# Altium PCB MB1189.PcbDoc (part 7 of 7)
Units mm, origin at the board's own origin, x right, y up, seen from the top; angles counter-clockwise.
Board outline 60.03 x 127.03 mm, 6 copper layers (TOP, L2_GND, L3_VCC, L4_SIG, L5_GND, BOTTOM), stack 1.58 mm thick; 273 components, 264 nets, 1114 pads, 811 vias.
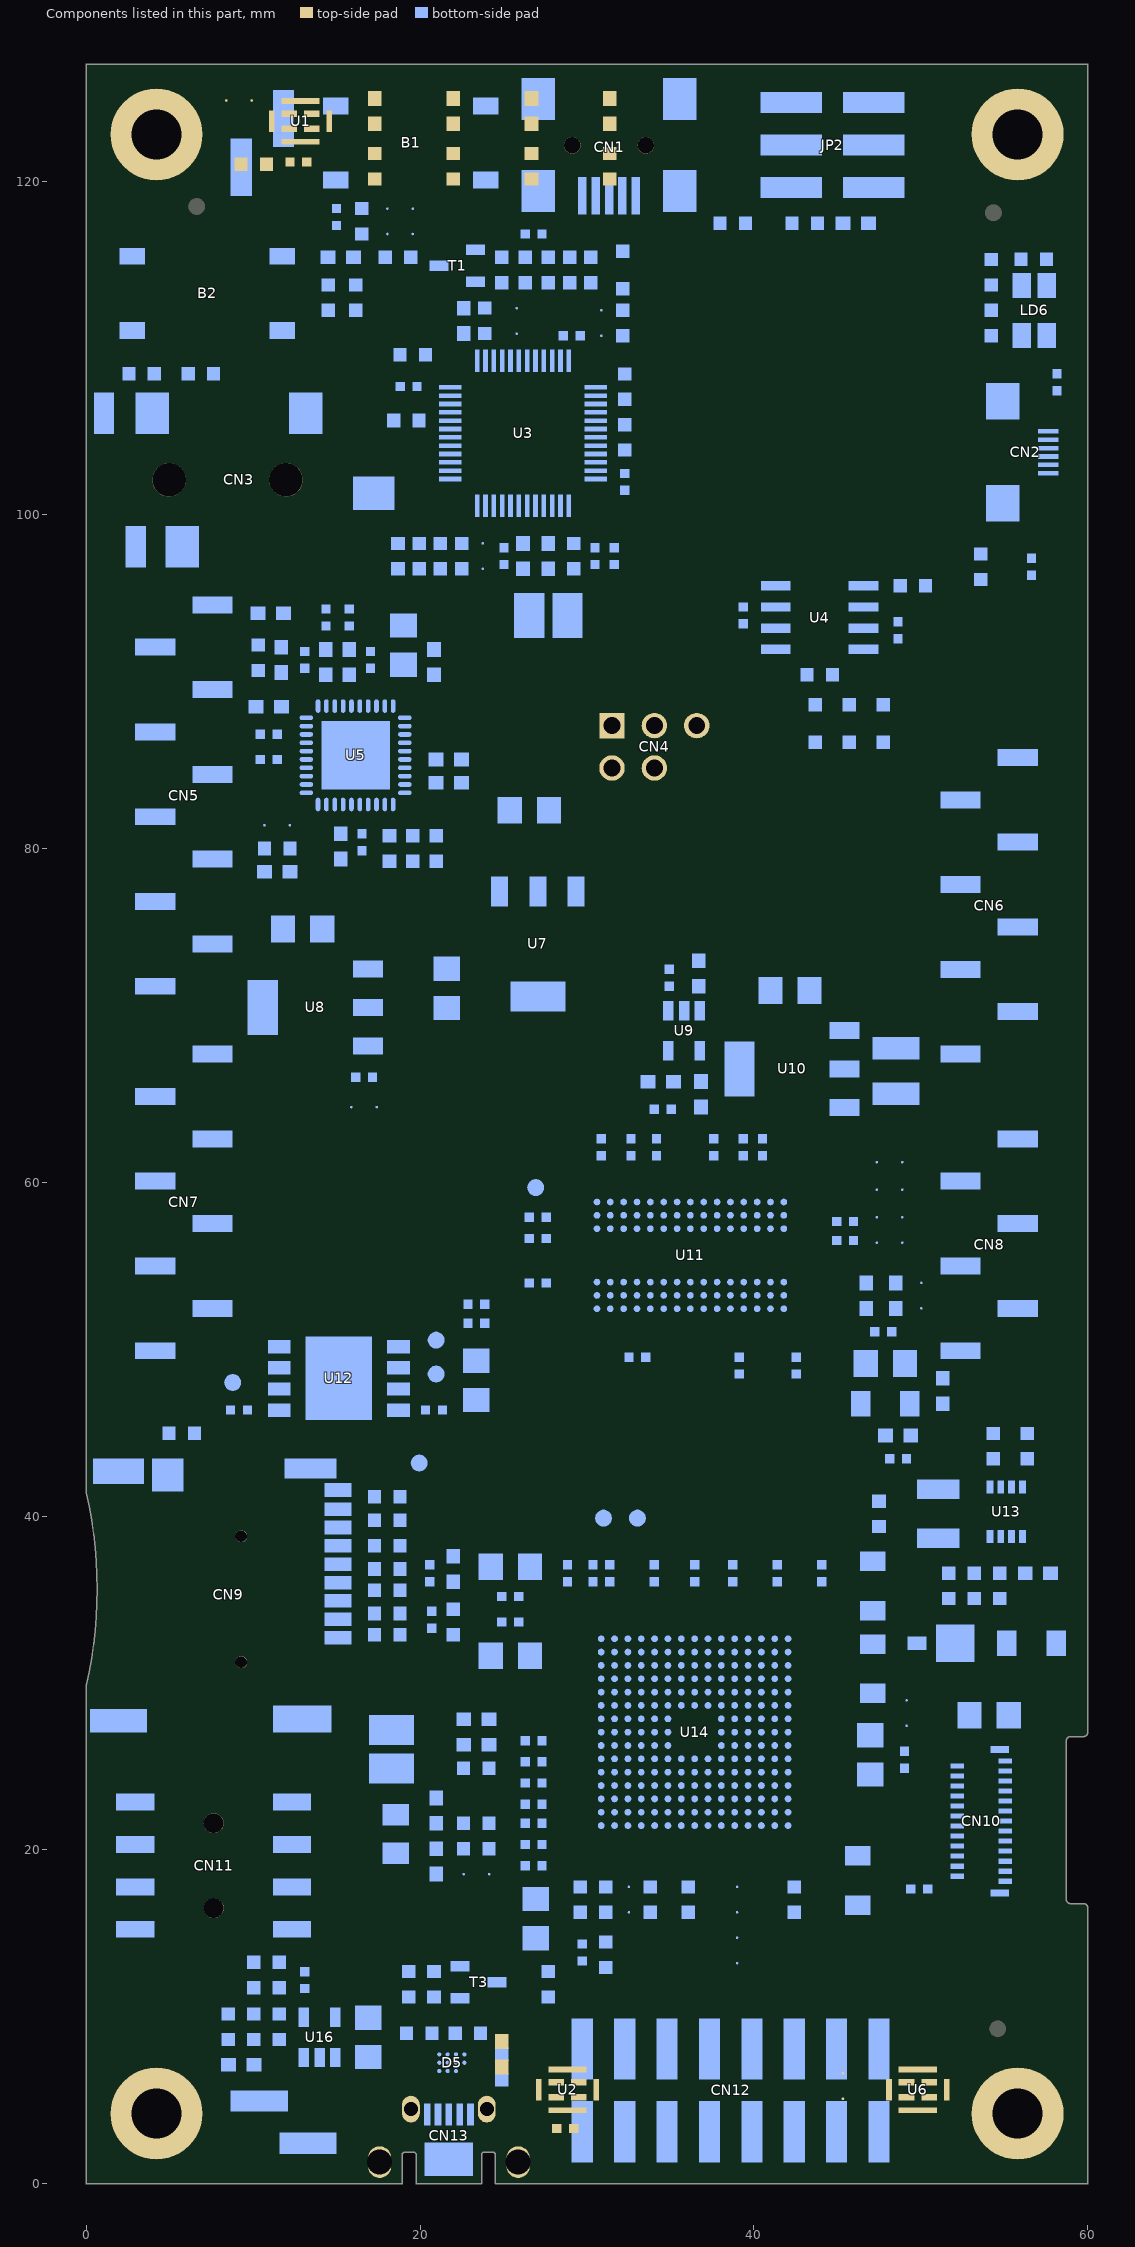
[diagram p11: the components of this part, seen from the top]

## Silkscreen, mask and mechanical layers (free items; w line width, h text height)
Top Overlay:
  lines w0.2: 10.795,122.834 10.541,122.834 10.541,121.793 11.659,121.793 11.659,122.047 ; 26.797,4.851 26.543,4.851 26.543,3.81 27.661,3.81 27.661,4.064 ; 47.799,4.851 47.545,4.851 47.545,3.81 48.663,3.81 48.663,4.064 ; 0,-0.042 0,29.804 ; 0,-0.042 18.917,-0.042 ; 0,-0.042 18.917,-0.042 ; 0,-0.042 0,29.804 ; 0,29.804 ccw(c-25.59,35.582) 0,41.361 ; 0,41.361 0,126.958 ; 0,41.361 0,126.958 ; 0,126.958 60,126.958 ; 0,126.958 60,126.958 ; 18.917,-0.042 18.917,1.744 ; 18.917,-0.042 18.917,1.744 ; 18.917,1.744 19.017,1.844 ; 18.917,1.744 19.017,1.844 ; 19.017,1.844 19.667,1.844 ; 19.017,1.844 19.667,1.844 ; 19.667,1.844 19.767,1.744 ; 19.667,1.844 19.767,1.744 ; 19.767,-0.042 19.767,1.744 ; 19.767,-0.042 23.667,-0.042 ; 19.767,-0.042 23.667,-0.042 ; 19.767,-0.042 19.767,1.744 ; 23.667,-0.042 23.667,1.744 ; 23.667,-0.042 23.667,1.744 ; 23.667,1.744 23.767,1.844 ; 23.667,1.744 23.767,1.844 ; 23.767,1.844 24.417,1.844 ; 23.767,1.844 24.417,1.844 ; 24.417,1.844 24.517,1.744 ; 24.417,1.844 24.517,1.744 ; 24.517,-0.042 24.517,1.744 ; 24.517,-0.042 60,-0.042 ; 24.517,-0.042 60,-0.042 ; 24.517,-0.042 24.517,1.744 ; 58.713,16.976 ccw(c58.967,16.976) 58.967,16.722 ; 58.713,16.976 ccw(c58.967,16.976) 58.967,16.722 ; 58.713,16.976 58.713,26.501 ; 58.713,16.976 58.713,26.501 ; 58.713,26.501 cw(c58.967,26.501) 58.967,26.755 ; 58.713,26.501 cw(c58.967,26.501) 58.967,26.755 ; 58.967,16.722 59.746,16.722 ; 58.967,16.722 59.746,16.722 ; 58.967,26.755 59.746,26.755 ; 58.967,26.755 59.746,26.755 ; 59.746,16.722 cw(c59.746,16.468) 60,16.468 ; 59.746,16.722 cw(c59.746,16.468) 60,16.468 ; 59.746,26.755 ccw(c59.746,27.009) 60,27.009 ; 59.746,26.755 ccw(c59.746,27.009) 60,27.009 ; 60,-0.042 60,16.468 ; 60,-0.042 60,16.468 ; 60,27.009 60,126.958 ; 60,27.009 60,126.958 ; 0.26,10.027 60,10.027 60,116.957 0.26,116.957 0.26,10.027 ; 11.43,58.547 11.43,59.944 12.827,59.944 12.827,58.547 11.43,58.547 ; 11.43,60.579 11.43,61.976 12.827,61.976 12.827,60.579 11.43,60.579 ; 21.336,5.8 22.479,5.8 22.479,9.356 21.336,9.356 21.336,5.8 ; 34,97.495 52,97.495 52,115.495 34,115.495 34,97.495
  text "H" at 46.68,121.509 h10
  text "J" at 35.56,118.727 h16
  text "C" at 47.74,118.601 h5
  text "www.st.com/stm32f4-discovery" at 12.99,117.92 h2.3
  text "S" at 11.752,60.762 h2
  text "B" at 11.705,58.712 h2
  text "MB1189C" at 9.11,7.87 h2.5
  text "STM32F469I-DISCO" at 29.93,7.85 h2.6
  text "VBUS" at 22.358,5.891 h1.4 r90
  text "E" at 34.303,4.755 h5
  text "F" at 38.98,4.25 h5
  text "I" at 14.38,3.169 h5
  text "G" at 8.59,3.141 h5
  text "S" at 36.357,0.48 h5
  text "TOP SILKSCREEN" at 55.499,-49.276 h1.52
  text ".GTO" at 97.5,-49.47 h1.52
Bottom Overlay:
  drawing of 324 lines, arcs and shapes, not listed
  text "RESET" at 18.662,125.652 h2
  text "GND" at 10.332,124.465 h1.7
  text "E5V" at 52.204,124.369 h2
  text "STLK" at 52.668,121.602 h2
  text "USBST-LINK" at 37.242,118.583 h2 r270
  text "USB" at 52.177,118.342 h2
  text "USER" at 4.666,117.082 h2
  text "5V" at 49.923,116.029 h2
  text "COM" at 58.761,113.577 h1.7 r270
  text "A" at 20.145,99.311 h1.7
  text "TS" at 59.514,98.602 h2
  text "AUDIO JACK" at 15.829,97.717 h2
  text "AUDIO JACK" at 15.829,97.717 h2
  text "D15" at 2.152,94.309 h1.6
  text "D14" at 1.945,91.941 h1.5
  text "A" at 49.982,89.434 h2
  text "AVDD" at 3.307,89.12 h1.6
  text "GND" at 2.578,86.58 h1.6
  text "D13" at 2.158,84.055 h1.6
  text "IOREF5" at 59.777,82.504 h1.7
  text "D12" at 2.161,81.508 h1.6
  text "NRST" at 59.845,79.976 h1.6
  text "D11" at 2.152,79.058 h1.6
  text "3V3" at 59.656,77.31 h1.6
  text "D10" at 2.179,76.421 h1.6
  text "5V" at 59.642,74.911 h1.6
  text "D9" at 1.499,74.015 h1.6
  text "GND" at 59.825,72.356 h1.6
  text "D8" at 1.508,71.221 h1.6
  text "GND" at 59.907,69.9 h1.6
  text "VIN" at 59.845,67.404 h1.6
  text "D7" at 1.496,67.166 h1.6
  text "B" at 10.555,65.002 h2
  text "D6" at 1.508,64.615 h1.6
  text "D5" at 1.487,62.338 h1.6
  text "A0" at 59.749,62.206 h1.6
  text "B" at 24.994,60.833 h1.5
  text "A1" at 59.749,59.894 h1.6
  text "D4" at 1.523,59.774 h1.6
  text "B" at 24.994,58.801 h1.5
  text "D3" at 1.493,57.164 h1.6
  text "A2" at 59.749,57.089 h1.6
  text "A3" at 59.749,54.696 h1.6
  text "D2" at 1.496,54.597 h1.6
  text "D1" at 1.487,52.201 h1.6
  text "A4" at 59.749,52.167 h1.6
  text "D0" at 1.514,49.495 h1.6
  text "A5" at 59.741,49.511 h1.6
  text "uSB" at 8.94,42.982 h2
  text "B" at 17.395,42.522 h2
  text "C" at 27.033,27.552 h2
  text "RFEEPROM" at 7.832,24.624 h1.8
  text "C" at 15.002,23.784 h2
  text "DSI  LCD" at 57.082,18.298 h2 r270
  text "FAULT" at 7.421,7.825 h1.9
  text "EXT" at 51.695,5.142 h2
  text "IDD" at 8.966,0.812 h2
  text "USB USER" at 26.992,0.567 h2 r270
  text ".GBO" at -7.9,-49.12 h1.8
  text "BOTTOM SILKSCREEN" at 27.457,-49.276 h1.8
Top Paste:
  text "SOLDER PASTE (PRIMARY)" at 55.499,-49.276 h1.52
Bottom Paste:
  text "BOTTOM SOLDER PASTE" at 55.499,-49.276 h1.52
Top Solder:
  text "TOP SOLDER MASK" at 55.499,-49.276 h1.52
  text ".GTS" at 97.47,-49.36 h1.52
Bottom Solder:
  text "BOTTOM SOLDER MASK" at 55.499,-49.276 h1.52
  text ".GBS" at 97.33,-49.29 h1.52
OUTLINE:
  lines w0.025: 0,29.845 0,0 18.917,0 18.917,1.785 19.017,1.885 19.667,1.885 19.767,1.785 19.767,0 23.667,0 23.667,1.785 23.767,1.885 24.417,1.885 24.517,1.785 24.517,0 60,0 60,16.51 ccw(c59.746,16.51) 59.746,16.764 58.967,16.764 cw(c58.967,17.018) 58.713,17.018 58.713,26.543 cw(c58.967,26.543) 58.967,26.797 ; 0,29.845 ccw(c-25.59,35.623) 0,41.402 ; -90.424,-128.016 -90.424,283.464 ; -90.424,-128.016 458.216,-128.016 ; -90.424,-128.016 -90.424,283.464 ; -90.424,-128.016 458.216,-128.016 ; -90.424,283.464 458.216,283.464 ; -90.424,283.464 458.216,283.464 ; -82.804,-120.396 326.136,-120.396 ; -82.804,-120.396 -82.804,275.844 ; -82.804,-120.396 -82.804,275.844 ; -82.804,-120.396 326.136,-120.396 ; -82.804,275.844 450.596,275.844 ; -82.804,275.844 450.596,275.844 ; 0,127 0,41.402 0,127 ; 0,127 60,127 ; 0,127 60,127 ; 58.967,26.797 59.746,26.797 ; 58.967,26.797 59.746,26.797 ; 59.746,26.797 ccw(c59.746,27.051) 60,27.051 ; 60,27.051 60,127 ; 60,27.051 60,127 ; 178.816,-116.586 188.976,-116.586 ; 178.816,-116.586 183.896,-128.016 ; 178.816,-116.586 183.896,-121.666 ; 178.816,-116.586 183.896,-121.666 ; 178.816,-116.586 188.976,-116.586 ; 178.816,-116.586 183.896,-128.016 ; 183.896,-128.016 188.976,-116.586 ; 183.896,-128.016 183.896,-110.236 183.896,-128.016 ; 183.896,-128.016 183.896,-120.396 183.896,-128.016 ; 183.896,-128.016 188.976,-116.586 ; 183.896,-121.666 188.976,-116.586 ; 183.896,-121.666 188.976,-116.586 ; 326.136,-120.396 450.596,-120.396 ; 326.136,-120.396 450.596,-120.396 ; 450.596,-120.396 450.596,123.444 ; 450.596,-120.396 450.596,123.444 ; 450.596,123.444 450.596,219.964 450.596,123.444 ; 450.596,275.844 450.596,82.804 450.596,275.844 ; 458.216,-128.016 458.216,283.464 ; 458.216,-128.016 458.216,283.464 ; -90.424,-21.336 -82.804,-21.336 -90.424,-21.336 ; -90.424,77.724 -82.804,77.724 -90.424,77.724 ; -90.424,176.784 -82.804,176.784 -90.424,176.784 ; 6.096,-128.016 6.096,-120.396 6.096,-128.016 ; 6.096,275.844 6.096,283.464 6.096,275.844 ; 94.996,-128.016 94.996,-120.396 94.996,-128.016 ; 94.996,275.844 94.996,283.464 94.996,275.844 ; 183.896,275.844 183.896,283.464 183.896,275.844 ; 272.796,-128.016 272.796,-120.396 272.796,-128.016 ; 272.796,275.844 272.796,283.464 272.796,275.844 ; 361.696,-128.016 361.696,-120.396 361.696,-128.016 ; 361.696,275.844 361.696,283.464 361.696,275.844 ; 450.596,-21.336 458.216,-21.336 450.596,-21.336 ; 450.596,77.724 458.216,77.724 450.596,77.724 ; 450.596,176.784 458.216,176.784 450.596,176.784
  text "6" at -37.084,278.384 h3.3
  text "6" at -37.084,278.384 h3.3
  text "5" at 51.816,278.384 h3.3
  text "5" at 51.816,278.384 h3.3
  text "4" at 140.716,278.384 h3.3
  text "4" at 140.716,278.384 h3.3
  text "3" at 229.616,278.384 h3.3
  text "3" at 229.616,278.384 h3.3
  text "2" at 318.516,278.384 h3.3
  text "2" at 318.516,278.384 h3.3
  text "1" at 407.416,278.384 h3.3
  text "1" at 407.416,278.384 h3.3
  text "D" at -87.884,219.964 h3.3
  text "D" at -87.884,219.964 h3.3
  text "D" at 453.136,219.964 h3.3
  text "D" at 453.136,219.964 h3.3
  text "C" at -87.884,120.904 h3.3
  text "C" at -87.884,120.904 h3.3
  text "C" at 453.136,120.904 h3.3
  text "C" at 453.136,120.904 h3.3
  text "B" at -87.884,26.924 h3.3
  text "B" at -87.884,26.924 h3.3
  text "B" at 453.136,26.924 h3.3
  text "B" at 453.136,26.924 h3.3
  text "A" at -87.884,-79.756 h3.3
  text "A" at -87.884,-79.756 h3.3
  text "A" at 453.136,-79.756 h3.3
  text "A" at 453.136,-79.756 h3.3
  text "6" at -37.084,-125.476 h3.3
  text "6" at -37.084,-125.476 h3.3
  text "5" at 51.816,-125.476 h3.3
  text "5" at 51.816,-125.476 h3.3
  text "4" at 140.716,-125.476 h3.3
  text "4" at 140.716,-125.476 h3.3
  text "3" at 229.616,-125.476 h3.3
  text "3" at 229.616,-125.476 h3.3
  text "2" at 318.516,-125.476 h3.3
  text "2" at 318.516,-125.476 h3.3
  text "1" at 407.416,-125.476 h3.3
  text "1" at 407.416,-125.476 h3.3
DIMENSION:
  lines w0.025: -17.486,0 -2.5,0 ; -17.486,127 -2.5,127 ; -9.612,67.691 5.056,67.691 ; -9.612,71.755 1.627,71.755 ; 0,129.5 0,134.58 ; 58.317,62.611 73.62,62.611 ; 58.317,85.471 73.62,85.471 ; 60,129.5 60,134.58 ; 71.12,105.936 71.12,85.471 ; -14.986,0 -14.986,66.04 -14.986,127 ; -14.986,0 -14.361,4 -15.611,4 -14.986,0 ; -14.986,127 -15.611,123 -14.361,123 -14.986,127 ; -7.112,67.691 -7.112,69.088 -7.112,71.755 ; -7.112,67.691 -7.737,63.691 -6.487,63.691 -7.112,67.691 ; -7.112,71.755 -6.487,75.755 -7.737,75.755 -7.112,71.755 ; 0,132.08 30.48,132.08 60,132.08 ; 0,132.08 4,131.455 4,132.705 0,132.08 ; 60,132.08 56,132.705 56,131.455 60,132.08 ; 71.12,62.611 71.12,85.471 ; 71.12,62.611 71.745,66.611 70.495,66.611 71.12,62.611 ; 71.12,62.611 71.12,85.471 ; 71.12,85.471 70.495,81.471 71.745,81.471 71.12,85.471
  text "60" at 28.727,133.286 h2.16
  text "22.86" at 69.913,95.122 h2.16 r90
  text "4.06" at -8.319,65.481 h2.16 r90
  text "127" at -16.192,63.36 h2.16 r90
  text "FAB DARWING & DRILL LEGEND" at 55.01,-49.33 h1.42
PLACE_BOUND_TOP:
  region: 8.135,118.491 8.106,118.79 8.019,119.077 7.877,119.342 7.687,119.574 7.455,119.764 7.19,119.906 6.903,119.993 6.604,120.022 6.305,119.993 6.018,119.906 5.842,119.812 5.753,119.764 5.521,119.574 5.331,119.342 5.189,119.077 5.102,118.79 5.073,118.491 5.102,118.192 5.189,117.905 5.331,117.64 5.521,117.408 5.753,117.218 5.842,117.17 6.018,117.076 6.305,116.989 6.604,116.96 6.903,116.989 7.19,117.076 7.455,117.218 7.687,117.408 7.877,117.64 8.019,117.905 8.106,118.192 8.135,118.491
  region: 55.887,118.11 55.858,118.409 55.771,118.696 55.629,118.961 55.439,119.193 55.207,119.383 54.942,119.525 54.655,119.612 54.356,119.641 54.057,119.612 53.77,119.525 53.594,119.431 53.505,119.383 53.273,119.193 53.083,118.961 52.941,118.696 52.854,118.409 52.825,118.11 52.854,117.811 52.941,117.524 53.083,117.259 53.273,117.027 53.505,116.837 53.594,116.789 53.77,116.695 54.057,116.608 54.356,116.579 54.655,116.608 54.942,116.695 55.207,116.837 55.439,117.027 55.629,117.259 55.771,117.524 55.858,117.811 55.887,118.11
  region: 56.141,9.271 56.112,9.57 56.025,9.857 55.883,10.122 55.693,10.354 55.461,10.544 55.196,10.686 54.909,10.773 54.61,10.802 54.311,10.773 54.024,10.686 53.848,10.592 53.759,10.544 53.527,10.354 53.337,10.122 53.195,9.857 53.108,9.57 53.079,9.271 53.108,8.972 53.195,8.685 53.337,8.42 53.527,8.188 53.759,7.998 53.848,7.95 54.024,7.856 54.311,7.769 54.61,7.74 54.909,7.769 55.196,7.856 55.461,7.998 55.693,8.188 55.883,8.42 56.025,8.685 56.112,8.972 56.141,9.271
PLACE_BOUND_BOTTOM:
  region: 8.135,118.491 8.106,118.79 8.019,119.077 7.877,119.342 7.687,119.574 7.455,119.764 7.19,119.906 6.903,119.993 6.604,120.022 6.305,119.993 6.018,119.906 5.842,119.812 5.753,119.764 5.521,119.574 5.331,119.342 5.189,119.077 5.102,118.79 5.073,118.491 5.102,118.192 5.189,117.905 5.331,117.64 5.521,117.408 5.753,117.218 5.842,117.17 6.018,117.076 6.305,116.989 6.604,116.96 6.903,116.989 7.19,117.076 7.455,117.218 7.687,117.408 7.877,117.64 8.019,117.905 8.106,118.192 8.135,118.491
  region: 55.887,118.11 55.858,118.409 55.771,118.696 55.629,118.961 55.439,119.193 55.207,119.383 54.942,119.525 54.655,119.612 54.356,119.641 54.057,119.612 53.77,119.525 53.594,119.431 53.505,119.383 53.273,119.193 53.083,118.961 52.941,118.696 52.854,118.409 52.825,118.11 52.854,117.811 52.941,117.524 53.083,117.259 53.273,117.027 53.505,116.837 53.594,116.789 53.77,116.695 54.057,116.608 54.356,116.579 54.655,116.608 54.942,116.695 55.207,116.837 55.439,117.027 55.629,117.259 55.771,117.524 55.858,117.811 55.887,118.11
  region: 56.141,9.271 56.112,9.57 56.025,9.857 55.883,10.122 55.693,10.354 55.461,10.544 55.196,10.686 54.909,10.773 54.61,10.802 54.311,10.773 54.024,10.686 53.848,10.592 53.759,10.544 53.527,10.354 53.337,10.122 53.195,9.857 53.108,9.57 53.079,9.271 53.108,8.972 53.195,8.685 53.337,8.42 53.527,8.188 53.759,7.998 53.848,7.95 54.024,7.856 54.311,7.769 54.61,7.74 54.909,7.769 55.196,7.856 55.461,7.998 55.693,8.188 55.883,8.42 56.025,8.685 56.112,8.972 56.141,9.271
ASSEMBLY_TOP:
  text "TOP ASSEMBLY" at 55.499,-49.276 h1.52
  text ".GTO" at 97.43,-49.36 h1.52
ASSEMBLY_BOTTOM:
  text "ASSEMBLY (SECONDARY)" at 31.115,-49.276 h1.52
TOP_TITLE_BLOCK:
  circle w0.254: c133.432,-56.1 r1.3
  region: 118.954,-57.193 108.198,-57.193 109.191,-54.7 117.049,-54.7 117.498,-53.941 119.706,-56.489
  region: 132.957,-48.863 117.43,-48.863 116.736,-50.639 115.525,-51.864 114.128,-50.004 114.128,-48.353 115.271,-46.956 116.707,-46.577 132.957,-46.577
  lines w0.254: 109.191,-54.7 117.983,-54.7 114.917,-51.162 cw(c116.721,-49.218) 116.961,-46.577 133.725,-46.577 132.963,-48.863 ; 112.505,-46.33 cw(c114.931,-47.301) 115.168,-44.698 ; 112.544,-46.298 108.198,-57.193 127.52,-57.193 ccw(c127.769,-54.458) 130.318,-55.478 ; 114.284,-50.233 119.706,-56.489 ; 114.538,-50.233 119.843,-56.354 ; 114.538,-49.979 119.843,-56.1 ; 114.636,-48.863 127.629,-48.863 ; 114.665,-49.852 119.97,-55.973 ; 114.792,-49.725 120.097,-55.846 ; 114.919,-49.598 120.224,-55.719 ; 115.046,-49.471 120.351,-55.592 ; 115.101,-47.518 120.406,-53.639 ; 115.169,-44.698 134.619,-44.698 130.319,-55.476 ; 115.173,-49.344 120.423,-55.402 ; 115.173,-49.09 120.478,-55.211 ; 115.173,-48.836 120.478,-54.957 ; 115.173,-47.947 120.478,-54.068 ; 115.3,-48.709 120.605,-54.83 ; 115.3,-48.328 120.605,-54.449 ; 116.672,-54.713 ccw(c116.777,-54.178) 117.074,-53.721 ; 117.758,-48.85 ccw(c117.732,-49.417) 117.402,-49.879 119.767,-52.608 cw(c117.963,-54.552) 118.695,-57.101 ; 124.039,-56.989 126.929,-48.609 ; 124.262,-56.939 127.131,-48.618 ; 124.389,-56.939 127.258,-48.618 ; 124.643,-56.939 127.512,-48.618 ; 124.897,-56.939 127.766,-48.618 ; 125.151,-56.939 128.02,-48.618 ; 125.405,-56.939 128.274,-48.618 ; 125.659,-56.939 128.528,-48.618 ; 125.913,-56.939 128.782,-48.618 ; 126.167,-56.939 129.036,-48.618 ; 126.375,-56.989 129.265,-48.609 ; 129.265,-48.863 132.957,-48.863 ; 132.289,-48.861 133.051,-46.575 ; 132.455,-48.863 133.217,-46.577 ; 132.709,-48.863 133.471,-46.577
  lines w0.3: 46.427,-56.079 106.427,-56.079 ; 46.427,-51.079 106.427,-51.079 ; 46.427,-46.079 106.427,-46.079 ; 86.427,-61.079 86.427,-46.079 ; 106.427,-61.079 106.427,-41.079 ; 124.039,-56.989 126.375,-56.989 ; 46.427,-61.079 136.427,-61.079 136.427,-41.079 46.427,-41.079 46.428,-61.079
  text "Project: '.Board_Name'" at 47.428,-44.295 h3
  text "Layer:" at 47.428,-49.379 h3
  text "Gerber:" at 87.416,-49.379 h3
  text "Variant: '.VariantName'" at 47.428,-54.379 h3
  text "Ref: '.Board_Reference'" at 87.543,-54.379 h3
  text "R" at 132.924,-56.862 h1.52
  text "Date: '.Board_Document_Date'" at 47.428,-59.379 h3
  text "Rev: '.Board_PCB_Revision'" at 87.486,-59.379 h3
BOTTOM_TITLE_BLOCK:
  circle w0.254: c-43.658,-56.426 r1.3
  region: -29.18,-57.519 -18.424,-57.519 -19.417,-55.026 -27.275,-55.026 -27.724,-54.267 -29.932,-56.815
  region: -43.183,-49.189 -27.656,-49.189 -26.962,-50.965 -25.751,-52.19 -24.354,-50.33 -24.354,-48.679 -25.497,-47.282 -26.933,-46.903 -43.183,-46.903
  lines w0.254: -43.697,-46.903 -42.935,-49.189 ; -43.443,-46.903 -42.681,-49.189 ; -43.277,-46.901 -42.515,-49.187 ; -43.189,-49.189 -43.951,-46.903 -27.187,-46.903 cw(c-26.947,-49.544) -25.143,-51.488 -28.209,-55.026 -19.417,-55.026 ; -43.183,-49.189 -39.491,-49.189 ; -40.546,-55.802 -44.845,-45.024 -25.395,-45.024 ; -40.545,-55.804 ccw(c-37.995,-54.784) -37.747,-57.519 -18.424,-57.519 -22.77,-46.624 ; -39.491,-48.935 -36.602,-57.315 ; -39.262,-48.944 -36.393,-57.265 ; -39.008,-48.944 -36.139,-57.265 ; -38.754,-48.944 -35.885,-57.265 ; -38.5,-48.944 -35.631,-57.265 ; -38.246,-48.944 -35.377,-57.265 ; -37.992,-48.944 -35.123,-57.265 ; -37.855,-49.189 -24.862,-49.189 ; -37.738,-48.944 -34.869,-57.265 ; -37.484,-48.944 -34.615,-57.265 ; -37.357,-48.944 -34.488,-57.265 ; -37.155,-48.935 -34.266,-57.315 ; -30.831,-55.156 -25.526,-49.034 ; -30.831,-54.775 -25.526,-48.653 ; -30.704,-55.537 -25.399,-49.415 ; -30.704,-55.283 -25.399,-49.161 ; -30.704,-54.394 -25.399,-48.272 ; -30.65,-55.728 -25.399,-49.669 ; -30.632,-53.965 -25.327,-47.844 ; -30.577,-55.918 -25.272,-49.796 ; -30.45,-56.045 -25.145,-49.923 ; -30.323,-56.172 -25.018,-50.05 ; -30.196,-56.299 -24.891,-50.177 ; -30.069,-56.68 -24.764,-50.558 ; -30.069,-56.426 -24.764,-50.304 ; -29.932,-56.815 -24.51,-50.558 ; -28.922,-57.427 cw(c-28.189,-54.878) -29.993,-52.934 -27.628,-50.205 ccw(c-27.958,-49.743) -27.984,-49.176 ; -27.301,-54.047 ccw(c-27.003,-54.504) -26.898,-55.039 ; -25.394,-45.024 cw(c-25.157,-47.627) -22.731,-46.656
  lines w0.3: -36.602,-57.315 -34.266,-57.315 ; -16.841,-61.405 -16.841,-41.405 ; -16.841,-56.405 43.159,-56.405 ; -16.841,-51.405 43.159,-51.405 ; -16.841,-46.405 43.159,-46.405 ; 3.159,-61.405 3.159,-46.405 ; -46.841,-61.405 43.159,-61.405 43.159,-41.405 -46.841,-41.405 -46.841,-61.405
  text "Project: '.Board_Name'" at 41.965,-44.621 h3
  text "Gerber:" at 1.976,-49.705 h3
  text "Layer:" at 41.965,-49.705 h3
  text "Ref: '.Board_Reference'" at 1.976,-54.705 h3
  text "Variant: '.VariantName'" at 41.965,-54.705 h3
  text "R" at -43.15,-57.188 h1.52
  text "Rev: '.Board_PCB_Revision'" at 2.033,-59.705 h3
  text "Date: '.Board_Document_Date'" at 41.965,-59.705 h3
REVISION_BLOCK:
  lines w0.025: 345.186,244.094 345.186,275.844 345.186,244.094 ; 345.186,249.174 450.596,249.174 345.186,249.174 ; 345.186,254.254 450.596,254.254 345.186,254.254 ; 345.186,259.334 450.596,259.334 345.186,259.334 ; 345.186,264.414 450.596,264.414 345.186,264.414 ; 345.186,269.494 450.596,269.494 345.186,269.494 ; 355.346,244.094 355.346,269.494 355.346,244.094 ; 411.226,244.094 411.226,269.494 411.226,244.094 ; 430.276,244.094 430.276,269.494 430.276,244.094
REVISION_DATA:
  lines w0.025: 29.21,51.13 43.155,51.13 43.155,59.944 29.21,59.944 29.21,51.13 ; 29.87,20.472 43.028,20.472 43.028,33.63 29.87,33.63 29.87,20.472
  text "REVISIONS" at 384.556,272.034 h2.16
  text "REVISIONS" at 384.556,272.034 h2.16
  text "REV" at 347.726,265.684 h1.91
  text "REV" at 347.726,265.684 h1.91
  text "DESCRIPTION" at 361.696,265.684 h1.91
  text "DESCRIPTION" at 361.696,265.684 h1.91
  text "DATE" at 416.306,265.684 h1.91
  text "DATE" at 416.306,265.684 h1.91
  text "APPROVED" at 434.086,265.684 h1.91
  text "APPROVED" at 434.086,265.684 h1.91
  text "1.0" at 347.726,260.604 h1.91
  text "1.0" at 347.726,260.604 h1.91
  text "EDITION ORIGINALE" at 361.696,260.604 h1.91
  text "EDITION ORIGINALE" at 361.696,260.604 h1.91
  text "2008-**-**" at 412.496,260.604 h1.91
  text "2008-**-**" at 412.496,260.604 h1.91
  text "***" at 438.15,260.604 h1.91
  text "***" at 438.15,260.604 h1.91
PIN_NUMBER:
NCLEGEND-1-6:
  lines w0.025: 100.101,102.425 100.305,102.425 ; 100.203,102.324 100.203,102.527 ; 96.959,81.597 97.909,79.304 100.203,78.353 102.497,79.304 103.447,81.597 102.497,83.891 100.203,84.842 97.909,83.891 96.959,81.597 ; 99.695,86.55 100.203,86.296 100.711,86.55 100.711,87.058 100.203,87.312 99.695,87.058 99.695,86.55 ; 99.708,70.688 100.203,71.679 100.698,70.688 99.708,70.688 ; 99.847,76.391 100.203,76.746 100.559,76.391 100.203,76.035 99.847,76.391 ; 99.873,49.517 ccw(c99.873,50.355) 99.873,51.194 100.533,51.194 ccw(c100.533,50.355) 100.533,49.517 99.873,49.517 ; 100.051,92.011 100.127,91.859 100.279,91.859 100.355,92.011 100.279,92.164 100.127,92.164 100.051,92.011 ; 100.076,97.091 100.33,97.091 100.33,97.346 100.076,97.346 100.076,97.091 ; 100.165,54.8 ccw(c100.165,55.562) 100.165,56.325 100.241,56.325 ccw(c100.241,55.562) 100.241,54.8 100.165,54.8 ; 100.203,58.763 cw(c100.203,60.77) 100.203,62.776 cw(c100.203,60.77) 100.203,58.763 ; 100.203,64.783 cw(c100.203,65.977) 100.203,67.17 cw(c100.203,65.977) 100.203,64.783
  lines w0.152: 94.615,52.959 186.868,52.959 ; 94.615,58.166 186.868,58.166 ; 94.615,63.373 186.868,63.373 ; 94.615,68.58 186.868,68.58 ; 94.615,73.787 186.868,73.787 ; 94.615,78.994 186.868,78.994 ; 94.615,84.201 186.868,84.201 ; 94.615,89.408 186.868,89.408 ; 94.615,94.615 186.868,94.615 ; 94.615,99.822 186.868,99.822 ; 94.615,105.029 186.868,105.029 ; 94.615,110.236 186.868,110.236 ; 94.615,115.443 186.868,115.443 ; 105.791,47.752 105.791,110.236 ; 121.691,47.752 121.691,110.236 ; 145.466,47.752 145.466,110.236 ; 162.941,47.752 162.941,110.236 ; 177.267,47.752 177.267,110.236 ; 94.615,47.752 94.615,121.793 186.868,121.793 186.868,47.752 94.615,47.752
  text "DRILL CHART: TOP to BOTTOM" at 120.929,118.935 h1.91
  text "ALL UNITS ARE IN MILS" at 124.739,112.585 h1.91
  text "FIGURE" at 95.631,107.379 h1.91
  text "SIZE" at 110.693,107.379 h1.91
  text "TOLERANCE" at 126.721,107.379 h1.91
  text "PLATED" at 149.631,107.379 h1.91
  text "ROTATION" at 164.008,107.379 h1.91
  text "QTY" at 179.781,107.379 h1.91
  text "8.0" at 111.455,101.473 h1.91
  text "+3.0/-3.0" at 126.721,101.473 h1.91
  text "PLATED" at 149.631,101.473 h1.91
  text "-" at 169.342,101.473 h1.91
  text "243" at 179.781,101.473 h1.91
  text "10.0" at 110.693,96.266 h1.91
  text "+3.0/-3.0" at 126.721,96.266 h1.91
  text "PLATED" at 149.631,96.266 h1.91
  text "-" at 169.342,96.266 h1.91
  text "247" at 179.781,96.266 h1.91
  text "12.0" at 110.693,91.059 h1.91
  text "+3.0/-3.0" at 126.721,91.059 h1.91
  text "PLATED" at 149.631,91.059 h1.91
  text "-" at 169.342,91.059 h1.91
  text "321" at 179.781,91.059 h1.91
  text "40.0" at 110.693,85.852 h1.91
  text "+3.0/-3.0" at 126.721,85.852 h1.91
  text "PLATED" at 149.631,85.852 h1.91
  text "-" at 169.342,85.852 h1.91
  text "5" at 181.305,85.852 h1.91
  text "118.0" at 109.931,80.645 h1.91
  text "+3.0/-3.0" at 126.721,80.645 h1.91
  text "PLATED" at 149.631,80.645 h1.91
  text "-" at 169.342,80.645 h1.91
  text "4" at 181.305,80.645 h1.91
  text "28.0" at 110.693,75.438 h1.91
  text "+2.0/-2.0" at 126.721,75.438 h1.91
  text "NON-PLATED" at 146.583,75.438 h1.91
  text "-" at 169.342,75.438 h1.91
  text "2" at 181.305,75.438 h1.91
  text "39.0" at 110.693,70.231 h1.91
  text "+2.0/-2.0" at 126.721,70.231 h1.91
  text "NON-PLATED" at 146.583,70.231 h1.91
  text "-" at 169.342,70.231 h1.91
  text "2" at 181.305,70.231 h1.91
  text "47.0" at 110.693,65.024 h1.91
  text "+2.0/-2.0" at 126.721,65.024 h1.91
  text "NON-PLATED" at 146.583,65.024 h1.91
  text "-" at 169.342,65.024 h1.91
  text "2" at 181.305,65.024 h1.91
  text "79.0" at 110.693,59.817 h1.91
  text "+2.0/-2.0" at 126.721,59.817 h1.91
  text "NON-PLATED" at 146.583,59.817 h1.91
  text "-" at 169.342,59.817 h1.91
  text "2" at 181.305,59.817 h1.91
  text "33.0x30.0" at 106.883,54.61 h1.91
  text "+5.0/-5.0" at 126.721,54.61 h1.91
  text "PLATED" at 149.631,54.61 h1.91
  text "90.000" at 165.532,54.61 h1.91
  text "2" at 181.305,54.61 h1.91
  text "59.0x33.0" at 106.883,49.403 h1.91
  text "+5.0/-5.0" at 126.721,49.403 h1.91
  text "PLATED" at 149.631,49.403 h1.91
  text "90.000" at 165.532,49.403 h1.91
  text "2" at 181.305,49.403 h1.91
  text "TOTAL HOLES:" at 157.074,44.196 h1.91
  text "832" at 179.781,44.196 h1.91
FAB_NOTES:
  drawing of 602 lines, arcs and shapes, not listed
  text "5" at 15.24,232.664 h2.54
  text "5" at 15.24,232.664 h2.54
  text "IMPEDANCE TABLE" at 23.114,232.156 h2.54
  text "IMPEDANCE TABLE" at 23.114,232.156 h2.54
  text "LAYER" at 21.209,224.688 h1.91
  text "LAYER" at 21.209,224.688 h1.91
  text "TOLERANCE" at 116.459,224.688 h1.91
  text "TOLERANCE" at 116.459,224.688 h1.91
  text "TRACE" at 40.259,224.434 h1.91
  text "TRACE" at 40.259,224.434 h1.91
  text "SPACEING" at 54.229,224.434 h1.91
  text "SPACEING" at 54.229,224.434 h1.91
  text "IMPEDANCE" at 73.279,224.434 h1.91
  text "IMPEDANCE" at 73.279,224.434 h1.91
  text "IMPEDANCE" at 96.139,224.434 h1.91
  text "IMPEDANCE" at 96.139,224.434 h1.91
  text "(mil)" at 41.529,222.148 h1.27
  text "(mil)" at 41.529,222.148 h1.27
  text "(Single end)" at 74.549,222.148 h1.27
  text "(Single end)" at 74.549,222.148 h1.27
  text "(mil)" at 56.769,221.894 h1.27
  text "(mil)" at 56.769,221.894 h1.27
  text "(Differential)" at 96.139,221.894 h1.27
  text "(Differential)" at 96.139,221.894 h1.27
  text "4" at 175.768,218.694 h1.91
  text "LAYER STUCK-UP" at 180.848,218.694 h1.91
  text "1,6" at 21.082,218.44 h1.91
  text "1,6" at 21.082,218.44 h1.91
  text "5.0" at 41.402,218.186 h1.91
  text "5.0" at 41.402,218.186 h1.91
  text "N/A" at 58.039,216.814 h1.91
  text "N/A" at 58.039,216.814 h1.91
  text "55 OHM" at 74.549,216.56 h1.91
  text "55 OHM" at 74.549,216.56 h1.91
  text "N/A" at 99.949,216.56 h1.91
  text "N/A" at 99.949,216.56 h1.91
  text "+/-10%" at 118.999,216.56 h1.91
  text "+/-10%" at 118.999,216.56 h1.91
  text "4.0" at 41.148,215.138 h1.91
  text "4.0" at 41.148,215.138 h1.91
  text "4" at 21.082,214.884 h1.91
  text "4" at 21.082,214.884 h1.91
  text "SOLDERMASK & SILKSCREEN" at 225.552,212.598 h1.52
  text "N/A" at 77.216,210.566 h1.91
  text "5.1" at 41.021,210.439 h1.91
  text "9.9" at 57.531,210.439 h1.91
  text "100 OHM" at 97.79,210.312 h1.91
  text "+/-10%" at 118.999,210.21 h1.91
  text "+/-10%" at 118.999,210.21 h1.91
  text "1,6" at 21.082,210.185 h1.91
  text "TOP     (0.5 oz cu+planted)" at 225.552,209.55 h1.52
  text "PREPREG  3.9 mil" at 192.024,205.359 h1.52
  text "90 OHM" at 97.638,204.064 h1.91
  text "+/-10%" at 119.151,204.013 h1.91
  text "6.1" at 40.894,203.835 h1.91
  text "8.9" at 57.404,203.708 h1.91
  text "N/A" at 77.343,203.479 h1.91
  text "1,6" at 21.209,203.327 h1.91
  text "LAYER 2 (1 oz)" at 225.552,201.93 h1.52
  text "CORE     4  mil" at 192.024,199.39 h1.52
  text "LAYER 3 (1 oz)" at 225.552,196.85 h1.52
  text "63 mil" at 169.875,195.008 h1.91
  text "PREPREG  ** mil" at 192.024,192.659 h1.52
  text "+/-10%" at 170.942,192.278 h1.27
  text "LAYER 4 (1 oz)" at 225.552,189.23 h1.52
  text "CORE     4  mil" at 192.024,186.69 h1.52
  text "LAYER 5 (1 oz)" at 225.552,184.15 h1.52
  text "PREPREG  3.9 mil" at 192.024,179.959 h1.52
  text "BOTTOM  (0.5 oz cu+planted)" at 225.552,176.53 h1.52
  text "SOLDERMASK & SILKSCREEN" at 225.552,173.482 h1.52
  text "6 LAYER STACKING" at 190.5,168.91 h1.91
  text "PCB SPECIFICATIONS:" at 267.64,137.693 h2.16
  text "A. MATERIAL;" at 267.64,132.613 h2.16
  text "FR-4," at 312.09,132.613 h2.16
  text "TG-170" at 336.22,132.613 h2.16
  text "TG-150" at 355.27,132.613 h2.16
  text "TG-140" at 376.86,132.613 h2.16
  text "B. MATERIAL FAMILY;" at 267.64,127.533 h2.16
  text "N/A." at 312.09,127.533 h2.16
  text "C. SOLDERMASK COLOR;" at 267.64,122.453 h2.16
  text "GREEN" at 315.9,122.453 h2.16
  text "BLUE" at 334.95,122.453 h2.16
  text "RED" at 356.54,122.453 h2.16
  text "BLACK" at 378.13,122.453 h2.16
  text "D. SILKSCREEN COLOR;" at 267.64,117.373 h2.16
  text "WHITE" at 315.9,117.373 h2.16
  text "YELLOW" at 334.95,117.373 h2.16
  text "BLACK" at 356.54,117.373 h2.16
  text "E. SURFACE FINISH;" at 267.64,112.293 h2.16
  text "ENIG" at 315.9,112.293 h2.16
  text "IMMERSION SILVER" at 334.95,112.293 h2.16
  text "IMMERSION TIN" at 378.13,112.293 h2.16
  text "HASL" at 315.9,107.213 h2.16
  text "HASL(PB-FREE)" at 334.95,107.213 h2.16
  text "GOLDEN FINGER" at 378.13,107.213 h2.16
  text "F. IMPEDANCE CONTROL;" at 267.64,102.133 h2.16
  text "NO" at 315.9,102.133 h2.16
  text "YES" at 334.95,102.133 h2.16
  text "(SEE IMPEDANCE TABLE FOR DETAIL INFORMATION)" at 340.03,102.133 h2.16
  text "G. THROUGH VIA;" at 267.64,97.053 h2.16
  text "PLUG THE VIAS WHICH ARE COVERED WITH SOLDERMASK ONE OR TWO SIDE." at 304.47,97.053 h2.16
  text "PLUG MATERIAL:" at 304.47,91.973 h2.16
  text "SOLDERMASK" at 345.11,91.973 h2.16
  text "NON-CONDUCTIVE EPOXY." at 378.13,91.973 h2.16
  text "H. STACK-UP;" at 267.64,86.893 h2.16
  text "SEE LAYER STACK-UP SEQUENCE FOR OVERALL THICKNESS." at 304.47,86.893 h2.16
  text "PCB REQUIREMENTS:" at 267.386,79.273 h2.16
  text "1. THIS BOARD WILL CONFORM TO:" at 266.116,74.193 h2.16
  text "IPC-A-600. CURRENT REV., CLASS II" at 266.116,70.383 h2.16
  text "IPC-6012, CURRENT REV., CLASS II" at 266.116,66.573 h2.16
  text "2. UNLESS OTHERWISE SPECIFIED ALL HOLE DIMENSIONS APPLY AFTER PLATING." at 266.116,61.239 h2.16
  text "ALL HOLES SHALL BE LOCATED WITHIN .003\" DIAMETER OF TRUE POSITION." at 266.116,57.429 h2.16
  text "3. PLATED HOLE WALL THICKNESS SHALL NOT BE LESS THAN .001 INCH MINIMUM" at 266.116,52.349 h2.16
  text "AVERAGE, WITH NO READING LESS THAN .0008 BY COROSS SECTION." at 270.688,48.793 h2.16
  text "4. MATERIAL FR4 RATING 94V-0 MINIMUM EPOXY GLASS LAMINATE." at 266.116,43.459 h2.16
  text "5. BOARD SHALL BE LPI SOLDER MASKED OVER BARE COPPER BOTH SIDES PER" at 266.116,38.887 h2.16
  text "IPC-SM-840 CLASS II." at 266.116,35.077 h2.16
  text "6. SILKSCREEN SHALL BE PERMANENT NON-CONDUCTIVE INK AND WITH NO OVERLAP" at 266.116,29.997 h2.16
  text "ON ANY COMPONENT PAD OR THROUGH HOLE." at 266.116,26.187 h2.16
  text "7. MFGR, TO LEGIBLY ETCH OR STAMP/SCREEN WITH PERMANENT NON-CONDUCTIVE INK" at 266.116,21.107 h2.16
  text "D. MFGR. LOGO" at 313.106,17.805 h2.16
  text "A. U.L. CODE" at 273.482,17.297 h2.16
  text "E. SUCCESSFUL ELECTRICAL BOARD TEST." at 313.106,14.249 h2.16
  text "B. DATE CODE" at 273.482,13.741 h2.16
  text "C. FLAMMABILITY RATING" at 273.482,10.185 h2.16
  text "8. REMOVE THE FLASHS WHICH SMALLER THAN HOLE SIZE." at 266.116,4.851 h2.16
  text "9. REMOVE ALL SHAPE EDGES AND BURRS .005 MAXIMUM." at 266.116,-0.229 h2.16
  text "10. PLEASE USE THE SUPPLIED IPC 356 NETLIST TO VERIFY BOARD BEFORE" at 266.116,-5.563 h2.16
  text "FABRICATING BOARD." at 266.116,-9.373 h2.16
LAY16:
  text "16" at 66.929,-45.466 h1.91
  text "LAYER 16(INTERNAL SIGNAL)" at 55.499,-49.276 h1.52
LAY4:
  text "4" at 68.199,-45.466 h1.91
  text "LAYER 4 (VTT PLANE)" at 55.499,-49.276 h1.52
LAY11:
  text "11" at 66.929,-45.466 h1.91
  text "LAYER 11(GND PLANE)" at 55.499,-49.276 h1.52
LAY5:
  text "5" at 68.199,-45.466 h1.91
  text "LAYER 5 (GND PLANE)" at 55.499,-49.276 h1.52
LAY8:
  text "8" at 68.199,-45.466 h1.91
  text "LAYER 8 (GND PLANE)" at 55.499,-49.276 h1.52
LAY17:
  text "17" at 66.929,-45.466 h1.91
  text "LAYER 17(GND PLANE)" at 55.499,-49.276 h1.52
LAY12:
  text "12" at 66.929,-45.466 h1.91
  text "LAYER 12(INTERNAL SIGNAL)" at 55.499,-49.276 h1.52
LAY3:
  text "3" at 68.199,-45.466 h1.91
  text "LAYER 3 (INTERNAL SIGNAL)" at 55.499,-49.276 h1.52
LAY6:
  text "6" at 68.199,-45.466 h1.91
  text "LAYER 6 (GND PLANE)" at 55.499,-49.276 h1.52
LAY14:
  text "14" at 66.929,-45.466 h1.91
  text "LAYER 14(INTERNAL SIGNAL)" at 55.499,-49.276 h1.52
ORIGIN:
  circle w0.025: c0,0 r2.54
  pour cut-out: 0,-2.54 0.221,-2.53 0.441,-2.501 0.657,-2.453 0.869,-2.387 1.073,-2.302 1.27,-2.2 1.457,-2.081 1.633,-1.946 1.796,-1.796 1.946,-1.633 2.081,-1.457 2.2,-1.27 2.302,-1.073 2.387,-0.869 2.453,-0.657 2.501,-0.441 2.53,-0.221 2.54,0 0,0 0,-2.54
  pour cut-out: 0,2.54 -0.221,2.53 -0.441,2.501 -0.657,2.453 -0.869,2.387 -1.073,2.302 -1.27,2.2 -1.457,2.081 -1.633,1.946 -1.796,1.796 -1.946,1.633 -2.081,1.457 -2.2,1.27 -2.302,1.073 -2.387,0.869 -2.453,0.657 -2.501,0.441 -2.53,0.221 -2.54,0 0,0 0,2.54
  lines w0.025: -3.81,0 3.81,0 ; 0,-3.81 0,3.81
LAY10:
  text "10" at 66.929,-45.466 h1.91
  text "LAYER 10(INTERNAL SIGNAL)" at 55.499,-49.276 h1.52
LAY15:
  text "15" at 66.929,-45.466 h1.91
  text "LAYER 15(GND PLANE)" at 55.499,-49.276 h1.52
LAYER_COUNT:
  text "/XX" at 66.929,-45.466 h1.91
DRAWING_ORIGIN:
  lines w0.025: -0.635,0 0.635,0 ; 0,-0.635 0,0.635
LAY7:
  text "7" at 68.199,-45.466 h1.91
  text "LAYER 7 (INTERNAL SIGNAL)" at 55.499,-49.276 h1.52
LAY2:
  lines w0.254: 15.113,58.547 15.113,59.944 16.51,59.944 16.51,58.547 15.113,58.547 ; 15.113,60.579 15.113,61.976 16.51,61.976 16.51,60.579 15.113,60.579
  text "2" at 68.199,-45.466 h1.91
  text "LAYER 2 (GND PLANE)" at 55.499,-49.276 h1.52
LAY9:
  text "9" at 68.199,-45.466 h1.91
  text "LAYER 9 (INTERNAL SIGNAL)" at 55.499,-49.276 h1.52
LAY13:
  text "13" at 66.929,-45.466 h1.91
  text "LAYER 13(GND PLANE)" at 55.499,-49.276 h1.52
MP_DRAWING:
  text "MUTI-PACK DRAWING" at 55.499,-49.276 h1.52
